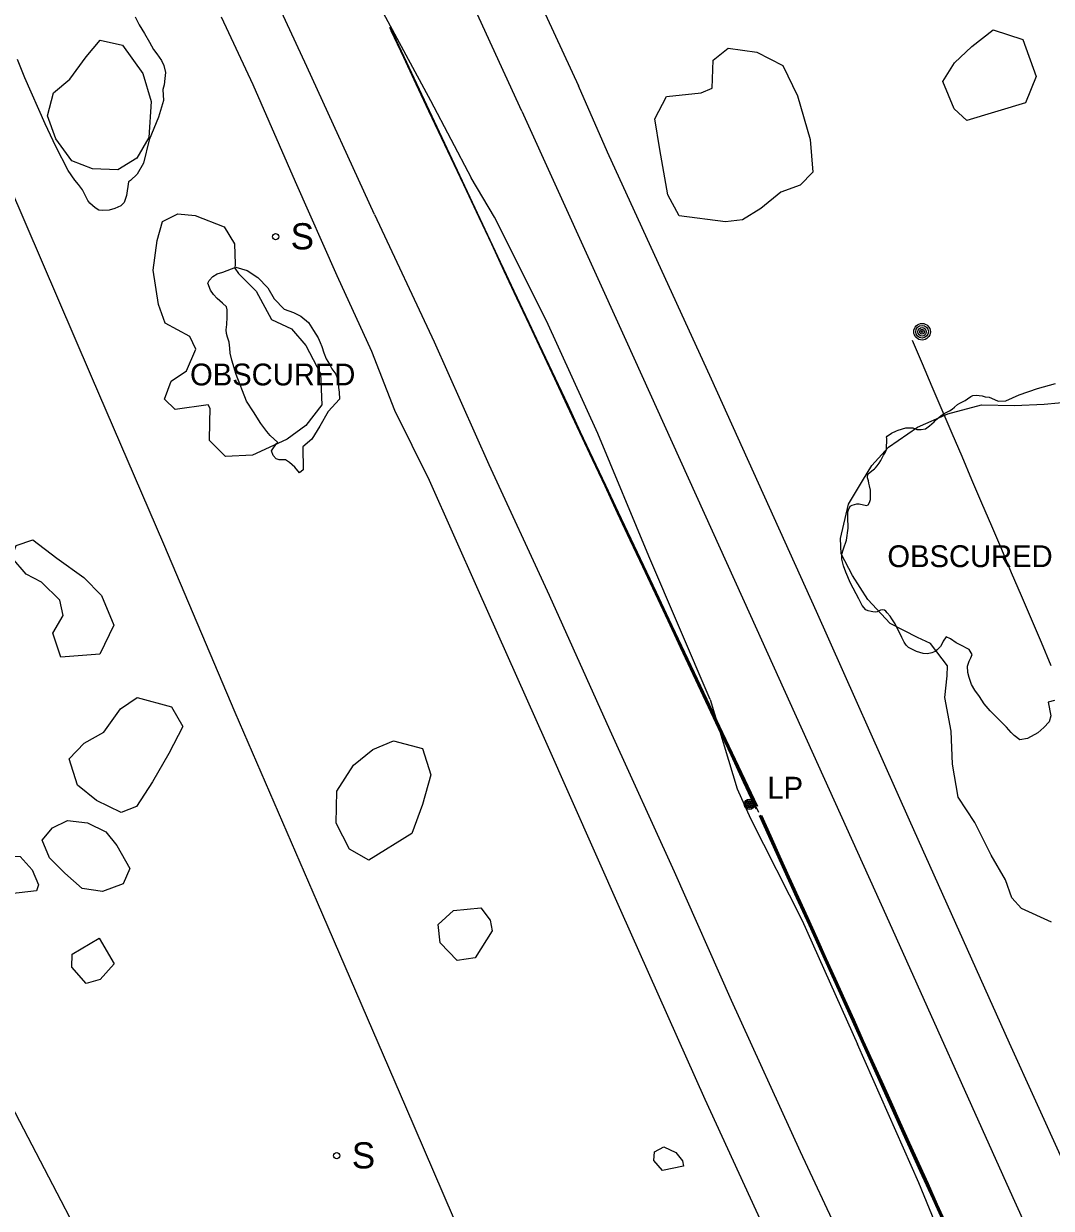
# Model space of a CAD drawing. Extents: x 368532 to 392481, y 10654822 to 10676899.
# Drawn here: x 377726.1 to 377961.7, y 10662774.9 to 10663046.4 of the extents above; entities that cross this region are included whole.
import ezdxf

# ---------------------------------------------------------------- set-up
doc = ezdxf.new("R2010")
doc.units = 0
for name, color, linetype in [('p_Catenary', 7, 'Continuous'), ('p_dtm obscured area', 7, 'Continuous'), ('p_railroad rr control', 7, 'Continuous'), ('p_road dirt road', 7, 'Continuous'), ('p_structure fence', 7, 'Continuous'), ('p_structure sign', 7, 'Continuous'), ('p_utility general pole', 7, 'Continuous'), ('p_veg woods', 7, 'Continuous')]:
    doc.layers.add(name, color=color, linetype=linetype)

msp = doc.modelspace()

# ---------------------------------------------------------------- linework, layer by layer
at = {"layer": 'p_Catenary'}
for points in [[(377894.14, 10662867.04), (377891.24, 10662873.19), (377888.34, 10662879.35), (377885.44, 10662885.5), (377882.55, 10662891.65), (377879.65, 10662897.8), (377876.75, 10662903.95), (377873.85, 10662910.11), (377870.96, 10662916.26), (377868.06, 10662922.41), (377865.16, 10662928.56), (377862.27, 10662934.72), (377859.37, 10662940.87), (377856.47, 10662947.02), (377853.57, 10662953.17), (377850.68, 10662959.32), (377847.78, 10662965.48), (377844.88, 10662971.63), (377841.98, 10662977.78), (377839.09, 10662983.93), (377836.19, 10662990.08), (377833.29, 10662996.24), (377830.4, 10663002.39), (377827.5, 10663008.54), (377824.6, 10663014.69), (377821.7, 10663020.84), (377818.81, 10663027), (377815.91, 10663033.15), (377813.01, 10663039.3), (377810.11, 10663045.45)], [(377810.27, 10663044.81), (377813.17, 10663038.68), (377816.07, 10663032.55), (377818.96, 10663026.42), (377821.86, 10663020.29), (377824.76, 10663014.16), (377827.66, 10663008.02), (377830.56, 10663001.89), (377833.45, 10662995.76), (377836.35, 10662989.63), (377839.25, 10662983.5), (377842.15, 10662977.37), (377845.05, 10662971.24), (377847.95, 10662965.11), (377850.84, 10662958.98), (377853.74, 10662952.85), (377856.64, 10662946.72), (377859.54, 10662940.59), (377862.44, 10662934.46), (377865.33, 10662928.32), (377868.23, 10662922.19), (377871.13, 10662916.06), (377874.03, 10662909.93), (377876.93, 10662903.8), (377879.83, 10662897.67), (377882.72, 10662891.54), (377885.62, 10662885.41), (377888.52, 10662879.28), (377891.42, 10662873.15), (377894.32, 10662867.02)], [(377894.06, 10662866.4), (377891.18, 10662872.57), (377888.29, 10662878.73), (377885.4, 10662884.89), (377882.51, 10662891.05), (377879.63, 10662897.21), (377876.74, 10662903.38), (377873.85, 10662909.54), (377870.96, 10662915.7), (377868.08, 10662921.86), (377865.19, 10662928.03), (377862.3, 10662934.19), (377859.41, 10662940.35), (377856.53, 10662946.51), (377853.64, 10662952.68), (377850.75, 10662958.84), (377847.86, 10662965), (377844.98, 10662971.16), (377842.09, 10662977.33), (377839.2, 10662983.49), (377836.31, 10662989.65), (377833.43, 10662995.81), (377830.54, 10663001.98), (377827.65, 10663008.14), (377824.76, 10663014.3), (377821.88, 10663020.46), (377818.99, 10663026.62), (377816.1, 10663032.79), (377813.21, 10663038.95), (377810.33, 10663045.11)], [(377810.39, 10663045), (377813.3, 10663038.81), (377816.2, 10663032.63), (377819.1, 10663026.45), (377822, 10663020.27), (377824.91, 10663014.08), (377827.81, 10663007.9), (377830.71, 10663001.72), (377833.62, 10662995.54), (377836.52, 10662989.36), (377839.42, 10662983.17), (377842.33, 10662976.99), (377845.23, 10662970.81), (377848.13, 10662964.63), (377851.03, 10662958.44), (377853.94, 10662952.26), (377856.84, 10662946.08), (377859.74, 10662939.9), (377862.65, 10662933.71), (377865.55, 10662927.53), (377868.45, 10662921.35), (377871.36, 10662915.17), (377874.26, 10662908.98), (377877.16, 10662902.8), (377880.07, 10662896.62), (377882.97, 10662890.44), (377885.87, 10662884.25), (377888.77, 10662878.07), (377891.68, 10662871.89), (377894.58, 10662865.71)], [(377961.71, 10662899.25), (377959.44, 10662904.58), (377957.16, 10662909.9), (377954.89, 10662915.22), (377952.61, 10662920.54), (377950.34, 10662925.87), (377948.06, 10662931.19), (377945.79, 10662936.51), (377943.51, 10662941.83), (377941.24, 10662947.15), (377938.96, 10662952.48), (377936.69, 10662957.8), (377934.41, 10662963.12), (377932.14, 10662968.44), (377929.86, 10662973.76)], [(377937.34, 10662770.82), (377934.51, 10662777.09), (377931.67, 10662783.36), (377928.84, 10662789.63), (377926, 10662795.9), (377923.17, 10662802.17), (377920.34, 10662808.44), (377917.5, 10662814.72), (377914.67, 10662820.99), (377911.83, 10662827.26), (377909, 10662833.53), (377906.17, 10662839.8), (377903.33, 10662846.07), (377900.5, 10662852.34), (377897.67, 10662858.61), (377894.83, 10662864.88)], [(377937.38, 10662771.41), (377935.27, 10662776.09), (377933.15, 10662780.76), (377931.04, 10662785.44), (377928.92, 10662790.12), (377926.81, 10662794.8), (377924.69, 10662799.48), (377922.58, 10662804.16), (377920.46, 10662808.84), (377918.35, 10662813.52), (377916.23, 10662818.2), (377914.12, 10662822.88), (377912, 10662827.56), (377909.89, 10662832.24), (377907.77, 10662836.92), (377905.66, 10662841.6), (377903.54, 10662846.28), (377901.43, 10662850.96), (377899.31, 10662855.63), (377897.2, 10662860.31), (377895.08, 10662864.99)], [(377895.27, 10662864.97), (377897.39, 10662860.28), (377899.51, 10662855.59), (377901.64, 10662850.9), (377903.76, 10662846.22), (377905.88, 10662841.53), (377908, 10662836.84), (377910.12, 10662832.15), (377912.24, 10662827.46), (377914.36, 10662822.77), (377916.48, 10662818.08), (377918.6, 10662813.4), (377920.72, 10662808.71), (377922.84, 10662804.02), (377924.97, 10662799.33), (377927.09, 10662794.64), (377929.21, 10662789.95), (377931.33, 10662785.27), (377933.45, 10662780.58), (377935.57, 10662775.89), (377937.69, 10662771.2)], [(377895.08, 10662864.65), (377897.2, 10662859.97), (377899.32, 10662855.28), (377901.44, 10662850.59), (377903.56, 10662845.9), (377905.68, 10662841.21), (377907.8, 10662836.52), (377909.92, 10662831.83), (377912.04, 10662827.14), (377914.16, 10662822.45), (377916.28, 10662817.77), (377918.4, 10662813.08), (377920.52, 10662808.39), (377922.64, 10662803.7), (377924.76, 10662799.01), (377926.88, 10662794.32), (377929, 10662789.63), (377931.12, 10662784.94), (377933.24, 10662780.25), (377935.36, 10662775.56), (377937.48, 10662770.88)]]:
    msp.add_lwpolyline(points, dxfattribs=at)
at = {"layer": 'p_dtm obscured area'}
for points in [[(377751.66, 10663047.89), (377752.64, 10663046.09), (377753.86, 10663044.1), (377754.98, 10663042.09), (377755.9, 10663040.44), (377756.69, 10663039.48), (377757.7, 10663037.93), (377758.26, 10663036.77), (377758.66, 10663035.17), (377758.48, 10663033.76), (377758.38, 10663032.38), (377758.06, 10663031.28), (377758.16, 10663028.74), (377757.08, 10663024.92), (377754.94, 10663019.74), (377753.64, 10663014.36), (377752.15, 10663011.91), (377750.64, 10663010.43), (377750.19, 10663010.08), (377749.73, 10663006.98), (377749.19, 10663005.38), (377748.4, 10663004.62), (377747.04, 10663004), (377745.73, 10663003.63), (377744.19, 10663003.57), (377743.36, 10663003.65), (377742.53, 10663004.15), (377741.32, 10663005.2), (377740.82, 10663005.81), (377740.13, 10663007.22), (377739.64, 10663008.25), (377738.72, 10663009.53), (377737.83, 10663010.53), (377736.35, 10663012.68), (377733.5, 10663018.21), (377731.08, 10663023.41), (377726.43, 10663033.97), (377724.75, 10663038.16)], [(377962.41, 10662891.3), (377960.97, 10662890.91), (377961.57, 10662887.74), (377961.18, 10662886.37), (377960.02, 10662885.09), (377958.6, 10662883.84), (377956.27, 10662882.58), (377954.47, 10662882.28), (377953.17, 10662883.24), (377952.47, 10662883.94), (377951.46, 10662885.18), (377950.48, 10662886.08), (377949.16, 10662887.46), (377947.66, 10662888.93), (377946.33, 10662890.54), (377945.28, 10662892.15), (377944.18, 10662893.67), (377943.4, 10662894.9), (377942.85, 10662896.53), (377942.6, 10662897.72), (377942.52, 10662899.13), (377942.85, 10662900.28), (377943.24, 10662901.08), (377943.58, 10662901.82), (377942.91, 10662902.95), (377940.79, 10662904.02), (377939.89, 10662904.45), (377938.61, 10662905.39), (377937.57, 10662905.88), (377936.94, 10662904.86), (377936.86, 10662904.65), (377936.31, 10662903.62), (377935.53, 10662902.9), (377935.08, 10662902.48), (377934.28, 10662902.16), (377933.3, 10662901.98), (377932.31, 10662902.04), (377931.53, 10662902.28), (377930.8, 10662902.49), (377930.19, 10662902.81), (377929.55, 10662903.12), (377929, 10662903.4), (377928.46, 10662903.98), (377928.01, 10662904.61), (377927.46, 10662905.68), (377925.93, 10662908.81), (377925.14, 10662909.98), (377924.73, 10662910.56), (377924.1, 10662911.33), (377923.77, 10662911.72), (377923.49, 10662911.94), (377922.9, 10662912.04), (377922.57, 10662912), (377921.79, 10662911.61), (377921.3, 10662911.54), (377920.8, 10662911.62), (377920.38, 10662911.68), (377919.7, 10662911.8), (377919.18, 10662912.04), (377918.38, 10662913.02), (377917.57, 10662914.57), (377915.7, 10662918.12), (377914.58, 10662920.65), (377914.04, 10662922.09), (377913.87, 10662923.03), (377913.71, 10662923.69), (377913.69, 10662924.83), (377914.09, 10662926.02), (377914.78, 10662928.02), (377915.12, 10662930.76), (377915.04, 10662933.3), (377915.09, 10662934.47), (377915.18, 10662934.97), (377915.57, 10662935.77), (377916.06, 10662936.05), (377917.16, 10662936.35), (377917.68, 10662936.34), (377919.36, 10662935.96), (377919.75, 10662936.09), (377920, 10662936.62), (377920.25, 10662937.33), (377920.29, 10662938.1), (377920.27, 10662938.74), (377920.28, 10662939.49), (377920, 10662940.48), (377919.84, 10662941.08), (377919.78, 10662941.64), (377919.6, 10662942.29), (377919.58, 10662942.74), (377919.76, 10662943.18), (377920.58, 10662943.9), (377920.9, 10662944.09), (377921.2, 10662944.33), (377921.44, 10662944.55), (377921.81, 10662945.07), (377922.21, 10662945.66), (377922.62, 10662946.28), (377922.96, 10662946.87), (377923.26, 10662947.5), (377923.69, 10662948.2), (377923.91, 10662948.76), (377924, 10662951.3), (377923.94, 10662951.62), (377924.06, 10662951.87), (377925.04, 10662952.51), (377926.18, 10662953.03), (377926.61, 10662953.2), (377928.37, 10662953.74), (377929.93, 10662953.72), (377930.85, 10662953.38), (377931.91, 10662953.39), (377932.84, 10662953.54), (377933.8, 10662954.2), (377934.82, 10662955.15), (377935.16, 10662955.51), (377936.4, 10662956.48), (377937.16, 10662957.04), (377938.34, 10662957.68), (377938.96, 10662958.05), (377939.55, 10662958.5), (377940.2, 10662959.07), (377940.7, 10662959.37), (377941.34, 10662959.71), (377941.95, 10662959.99), (377942.53, 10662960.37), (377943.22, 10662960.92), (377943.75, 10662961.12), (377944.53, 10662961.27), (377945.19, 10662961.16), (377945.85, 10662961.09), (377946.57, 10662960.88), (377947.44, 10662960.76), (377948.01, 10662960.53), (377949.55, 10662959.83), (377951.27, 10662959.97), (377954.36, 10662961.28), (377958.53, 10662962.78), (377962.7, 10662963.9)]]:
    msp.add_lwpolyline(points, dxfattribs=at)
msp.add_lwpolyline([(377784.37, 10662950.37), (377782.66, 10662952.01), (377781.86, 10662952.94), (377780.5, 10662954.76), (377778.8, 10662957.41), (377777.22, 10662959.87), (377774.88, 10662965.95), (377773.87, 10662969.28), (377773.49, 10662970.83), (377773.41, 10662972.02), (377773.27, 10662973.39), (377772.88, 10662974.54), (377772.61, 10662975.4), (377772.54, 10662976.23), (377772.74, 10662977.39), (377772.77, 10662979.14), (377772.79, 10662980.77), (377772.62, 10662981.48), (377771.7, 10662982.29), (377770.49, 10662983.37), (377769.66, 10662984.31), (377768.96, 10662985.3), (377768.33, 10662986.87), (377768.64, 10662987.48), (377769.52, 10662988.43), (377770.53, 10662989.01), (377771.8, 10662989.4), (377774.78, 10662990.54), (377777.36, 10662989.77), (377779.82, 10662988.2), (377782.09, 10662985.8), (377783.54, 10662983.34), (377785.87, 10662980.91), (377787.96, 10662980.16), (377789.71, 10662979.33), (377791.42, 10662977.91), (377792.54, 10662976.05), (377793.65, 10662974.39), (377794.07, 10662973.27), (377794.45, 10662972.38), (377794.98, 10662970.94), (377795.5, 10662969.59), (377796.23, 10662968.32), (377796.77, 10662967.3), (377797.21, 10662966.62), (377797.68, 10662966.03), (377797.99, 10662965.2), (377798.27, 10662964.1), (377798.33, 10662963.01), (377798.46, 10662961.94), (377798.53, 10662960.35), (377795.94, 10662957.51), (377794.03, 10662954.12), (377792.2, 10662951.17), (377790.14, 10662949.39), (377790.22, 10662944.16), (377789.34, 10662943.47), (377788.28, 10662944.7), (377787.07, 10662945.83), (377786.17, 10662946.4), (377784.67, 10662946.4), (377783.99, 10662946.61), (377783.3, 10662947.38), (377782.95, 10662948.45), (377784.1, 10662950.19)], close=True, dxfattribs=at)
at = {"layer": 'p_railroad rr control'}
for points in [[(377634.58, 10663433.17), (377659.74, 10663394.03), (377692.69, 10663340.47), (377714.88, 10663302.64), (377744.62, 10663249.8), (377770.39, 10663201.87), (377796.79, 10663150.88), (377818.88, 10663105.98), (377834.7, 10663072.42), (377853.33, 10663032.08)], [(377840.31, 10663026.28), (377819.09, 10663072.66), (377798.47, 10663115.08), (377789.46, 10663133.86), (377768.78, 10663174.68), (377745.92, 10663218.55), (377723, 10663259.76), (377696.69, 10663305.72), (377675.57, 10663341.08), (377655.07, 10663374.31), (377624.68, 10663422.51), (377622.28, 10663426.07)], [(377533.14, 10663389.06), (377560.85, 10663341.04), (377588.79, 10663290.47), (377613.7, 10663243.12), (377634.41, 10663202.3), (377655.63, 10663158.5), (377673.78, 10663119.33), (377695.32, 10663071.97), (377715.09, 10663027.07), (377741.59, 10662965.55)], [(378042.9, 10662611.89), (378024.32, 10662653.23), (377997.98, 10662711.65), (377976.23, 10662759.59), (377952.15, 10662812.77), (377929.23, 10662863.82), (377907.89, 10662911.65), (377883.8, 10662964.88), (377859.94, 10663016.94), (377853.33, 10663032.08)], [(377840.31, 10663026.28), (377864.2, 10662973.82), (377892.78, 10662910.74), (377923.77, 10662842.18), (377952.9, 10662777.36), (377979.77, 10662718.13), (378010.76, 10662648.86), (378029.98, 10662606.04)], [(377741.59, 10662965.55), (377758.16, 10662927.17), (377774.58, 10662888.59), (377793.4, 10662845.07), (377813.68, 10662798.23), (377830.99, 10662757.99), (377850.44, 10662712.39), (377868.92, 10662669.33), (377889.14, 10662623.18), (377910.01, 10662574.15), (377923.89, 10662542.32)], [(377872.51, 10662512.94), (377854.1, 10662547.75), (377833.48, 10662587.51), (377809.12, 10662634), (377784.88, 10662680.38), (377759.49, 10662728.97), (377734.76, 10662776.63), (377712.8, 10662818.59), (377687.78, 10662866.46), (377662.32, 10662915.92)]]:
    msp.add_lwpolyline(points, dxfattribs=at)
at = {"layer": 'p_road dirt road'}
for p, q in [((377791.02, 10663036.53), (377771.19, 10663079.53)), ((377807.53, 10663050.67), (377819.37, 10663028.73)), ((377806.56, 10663002.65), (377791.02, 10663036.53)), ((377819.37, 10663028.73), (377828.73, 10663011.04)), ((377834.09, 10663002.02), (377828.73, 10663011.04)), ((377806.56, 10663002.65), (377820.2, 10662973.46)), ((377845.97, 10662978.29), (377834.09, 10663002.02)), ((377857.72, 10662952.46), (377845.97, 10662978.29)), ((377820.2, 10662973.46), (377832.77, 10662945.35)), ((377869.48, 10662924.36), (377857.72, 10662952.46)), ((377832.77, 10662945.35), (377846.59, 10662915.37)), ((377883.52, 10662891.5), (377869.48, 10662924.36)), ((377846.59, 10662915.37), (377860.5, 10662884.45)), ((377883.52, 10662891.5), (377889.72, 10662871.04)), ((377860.5, 10662884.45), (377875.28, 10662852.07)), ((377889.72, 10662871.04), (377892.76, 10662864.24)), ((377892.76, 10662864.24), (377904.57, 10662840.88)), ((377875.28, 10662852.07), (377888.33, 10662822.62)), ((377904.57, 10662840.88), (377917.27, 10662812.53)), ((377888.33, 10662822.62), (377904.12, 10662787.95)), ((377931.3, 10662780.77), (377917.27, 10662812.53)), ((377904.12, 10662787.95), (377917.57, 10662759.32)), ((377943.68, 10662751.1), (377931.3, 10662780.77))]:
    msp.add_line(p, q, dxfattribs=at)
at = {"layer": 'p_structure fence'}
for p, q in [((377771.38, 10663047.91), (377778.67, 10663032.39)), ((377778.67, 10663032.39), (377788.34, 10663010.2)), ((377788.34, 10663010.2), (377797.92, 10662988.63)), ((377797.92, 10662988.63), (377805.84, 10662971.28)), ((377805.84, 10662971.28), (377811.16, 10662957.79)), ((377811.16, 10662957.79), (377819.1, 10662941.75)), ((377819.1, 10662941.75), (377830.24, 10662916.74)), ((377830.24, 10662916.74), (377845.73, 10662881.97)), ((377845.73, 10662881.97), (377862.96, 10662843.23)), ((377862.96, 10662843.23), (377882.32, 10662799.95)), ((377882.32, 10662799.95), (377902.96, 10662754.86))]:
    msp.add_line(p, q, dxfattribs=at)
at = {"layer": 'p_structure sign'}
for centre in [(377783.89, 10662997.53), (377797.91, 10662786.95)]:
    msp.add_circle(centre, 0.713, dxfattribs=at)
at = {"layer": 'p_utility general pole'}
for centre, radius in [((377932.08, 10662975.76), 1.9), ((377932.08, 10662975.76), 1.44), ((377932.08, 10662975.76), 0.973), ((377932.08, 10662975.76), 0.539), ((377932.08, 10662975.76), 0.192), ((377892.52, 10662867.48), 1.19), ((377892.52, 10662867.48), 0.901), ((377892.52, 10662867.48), 0.608), ((377892.52, 10662867.48), 0.337), ((377892.52, 10662867.48), 0.12)]:
    msp.add_circle(centre, radius, dxfattribs=at)
at = {"layer": 'p_veg woods'}
for points in [[(377942.32, 10663024.18), (377939.4, 10663026.83), (377936.81, 10663033.11), (377939.53, 10663037.41), (377943.5, 10663041.14), (377948.36, 10663044.98), (377955.14, 10663042.72), (377958.27, 10663034.25), (377955.82, 10663028.22)], [(377741.91, 10663013.11), (377737.2, 10663014.9), (377733.53, 10663019.99), (377731.61, 10663025.24), (377732.96, 10663030.49), (377736.72, 10663033.63), (377740.47, 10663038.79), (377743.65, 10663042.55), (377748.79, 10663041.43), (377753.46, 10663034.95), (377755.33, 10663028.56), (377754.83, 10663020.24), (377752.11, 10663015.51), (377747.71, 10663012.86)], [(377876.43, 10663002.34), (377873.78, 10663007.16), (377871.99, 10663017.55), (377870.82, 10663024.57), (377873.46, 10663029.66), (377881.42, 10663030.49), (377883.98, 10663031.57), (377884.16, 10663037.96), (377887.63, 10663040.71), (377894.18, 10663039.82), (377900.19, 10663036.78), (377903.51, 10663029.79), (377906.44, 10663019.82), (377907.04, 10663012.35), (377904.15, 10663009.32), (377899.71, 10663007.76), (377895.13, 10663003.99), (377890.9, 10663001.4), (377887.05, 10663000.95)], [(377758.61, 10662977.71), (377757.02, 10662982.04), (377755.86, 10662989.86), (377756.71, 10662996.66), (377757.98, 10663001.01), (377761.49, 10663002.78), (377765.46, 10663002.37), (377772.08, 10662999.78), (377774.5, 10662995.92), (377774.63, 10662991.27), (377774.51, 10662990.32), (377775.39, 10662989.1), (377779.4, 10662985.06), (377782.92, 10662978.58), (377787.52, 10662976.46), (377790.84, 10662972.64), (377794.17, 10662966.23), (377794.51, 10662959.03), (377790.83, 10662954.25), (377786.53, 10662951.12), (377782.43, 10662949.26), (377778.59, 10662947.46), (377772.38, 10662947.18), (377768.75, 10662950.85), (377768.78, 10662955.06), (377768.87, 10662958.19), (377768.45, 10662959.04), (377760.9, 10662957.95), (377758.41, 10662960.32), (377759.97, 10662964.41), (377763.43, 10662966.83), (377765.63, 10662971.75), (377764.22, 10662974.71)], [(377734.68, 10662901.17), (377732.79, 10662906.69), (377735.2, 10662910.77), (377734.42, 10662914.28), (377730.19, 10662918.41), (377726.68, 10662920.25), (377723.4, 10662924.03), (377724.45, 10662926.79), (377728.21, 10662928.09), (377733.75, 10662923.92), (377739.91, 10662919.42), (377744, 10662915.34), (377746.81, 10662908.53), (377743.63, 10662901.9)], [(377742.84, 10662868.33), (377738.48, 10662871.87), (377736.6, 10662877.89), (377740.01, 10662881.52), (377744.55, 10662884.01), (377748.35, 10662889.33), (377752.17, 10662891.93), (377760.01, 10662889.79), (377762.59, 10662885.32), (377759.42, 10662879.15), (377755.65, 10662872.64), (377751.98, 10662866.98), (377748.48, 10662865.61)], [(377805.25, 10662854.68), (377800.81, 10662857.2), (377797.76, 10662863.17), (377797.92, 10662870.53), (377801.73, 10662876.45), (377806.19, 10662880.03), (377810.92, 10662882.04), (377817.58, 10662880.27), (377819.48, 10662874.26), (377817.55, 10662867.42), (377815.15, 10662860.79)], [(377735.57, 10662851.69), (377732.03, 10662855.19), (377730.4, 10662859.29), (377732.77, 10662862.1), (377736.2, 10662863.78), (377740.74, 10662863.22), (377744.98, 10662861.2), (377747.49, 10662858.02), (377750.44, 10662852.77), (377748.96, 10662849.29), (377744.17, 10662847.52), (377739.51, 10662848.19)], [(377723.12, 10662846.95), (377720.98, 10662848.11), (377718.29, 10662851.44), (377718.55, 10662852.66), (377723.01, 10662855.58), (377725.35, 10662855.53), (377728.07, 10662852.46), (377729.53, 10662849.06), (377729.08, 10662847.65)], [(377829.67, 10662832.29), (377825.51, 10662831.67), (377821.6, 10662835.76), (377821.14, 10662839.92), (377824.68, 10662843.15), (377830.92, 10662843.79), (377833.07, 10662840.93), (377833.5, 10662838.49)], [(377743.46, 10662836.84), (377746.91, 10662830.96), (377743.66, 10662827.37), (377740.49, 10662826.4), (377737.2, 10662830.14), (377737.29, 10662833.15)], [(377872.6, 10662783.57), (377870.58, 10662785.83), (377870.72, 10662787.85), (377872.87, 10662789.01), (377875.61, 10662787.67), (377877.14, 10662785.81), (377877.37, 10662784.54)]]:
    msp.add_lwpolyline(points, close=True, dxfattribs=at)
msp.add_lwpolyline([(377961.74, 10662840.49), (377954.91, 10662843.64), (377952.67, 10662846.07), (377951.17, 10662850.16), (377947.94, 10662855.86), (377944.18, 10662863.33), (377940.39, 10662869.14), (377939.05, 10662876.71), (377938.75, 10662884.22), (377937.33, 10662891.95), (377937.83, 10662896.95), (377937.91, 10662899.25), (377934, 10662904.31), (377931.04, 10662905.71), (377924.73, 10662908.94), (377919.66, 10662914.44), (377916.12, 10662919.89), (377913.56, 10662924.84), (377913.41, 10662928.36), (377915.18, 10662936.26), (377918.45, 10662941.58), (377920.55, 10662945.12), (377924.4, 10662949.34), (377931.05, 10662953.88), (377938.01, 10662956.98), (377945.7, 10662959.04), (377953.26, 10662958.85), (377960.06, 10662959.19), (377966.63, 10662959.82)], dxfattribs=at)

# ---------------------------------------------------------------- texts
at = {"layer": 'p_dtm obscured area'}
for p in [(377762.42, 10662963.47), (377922.27, 10662921.83)]:
    msp.add_text(' OBSCURED', height=5, dxfattribs=at).set_placement(p)
at = {"layer": 'p_structure sign'}
for p in [(377787.34, 10662994.64), (377801.36, 10662784.05)]:
    msp.add_text('S', height=6, dxfattribs=at).set_placement(p)
at = {"layer": 'p_utility general pole'}
msp.add_text('LP', height=5, dxfattribs=at).set_placement((377896.63, 10662868.78))

doc.saveas('drawing.dxf')
